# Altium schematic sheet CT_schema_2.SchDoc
size 384 x 228 mm
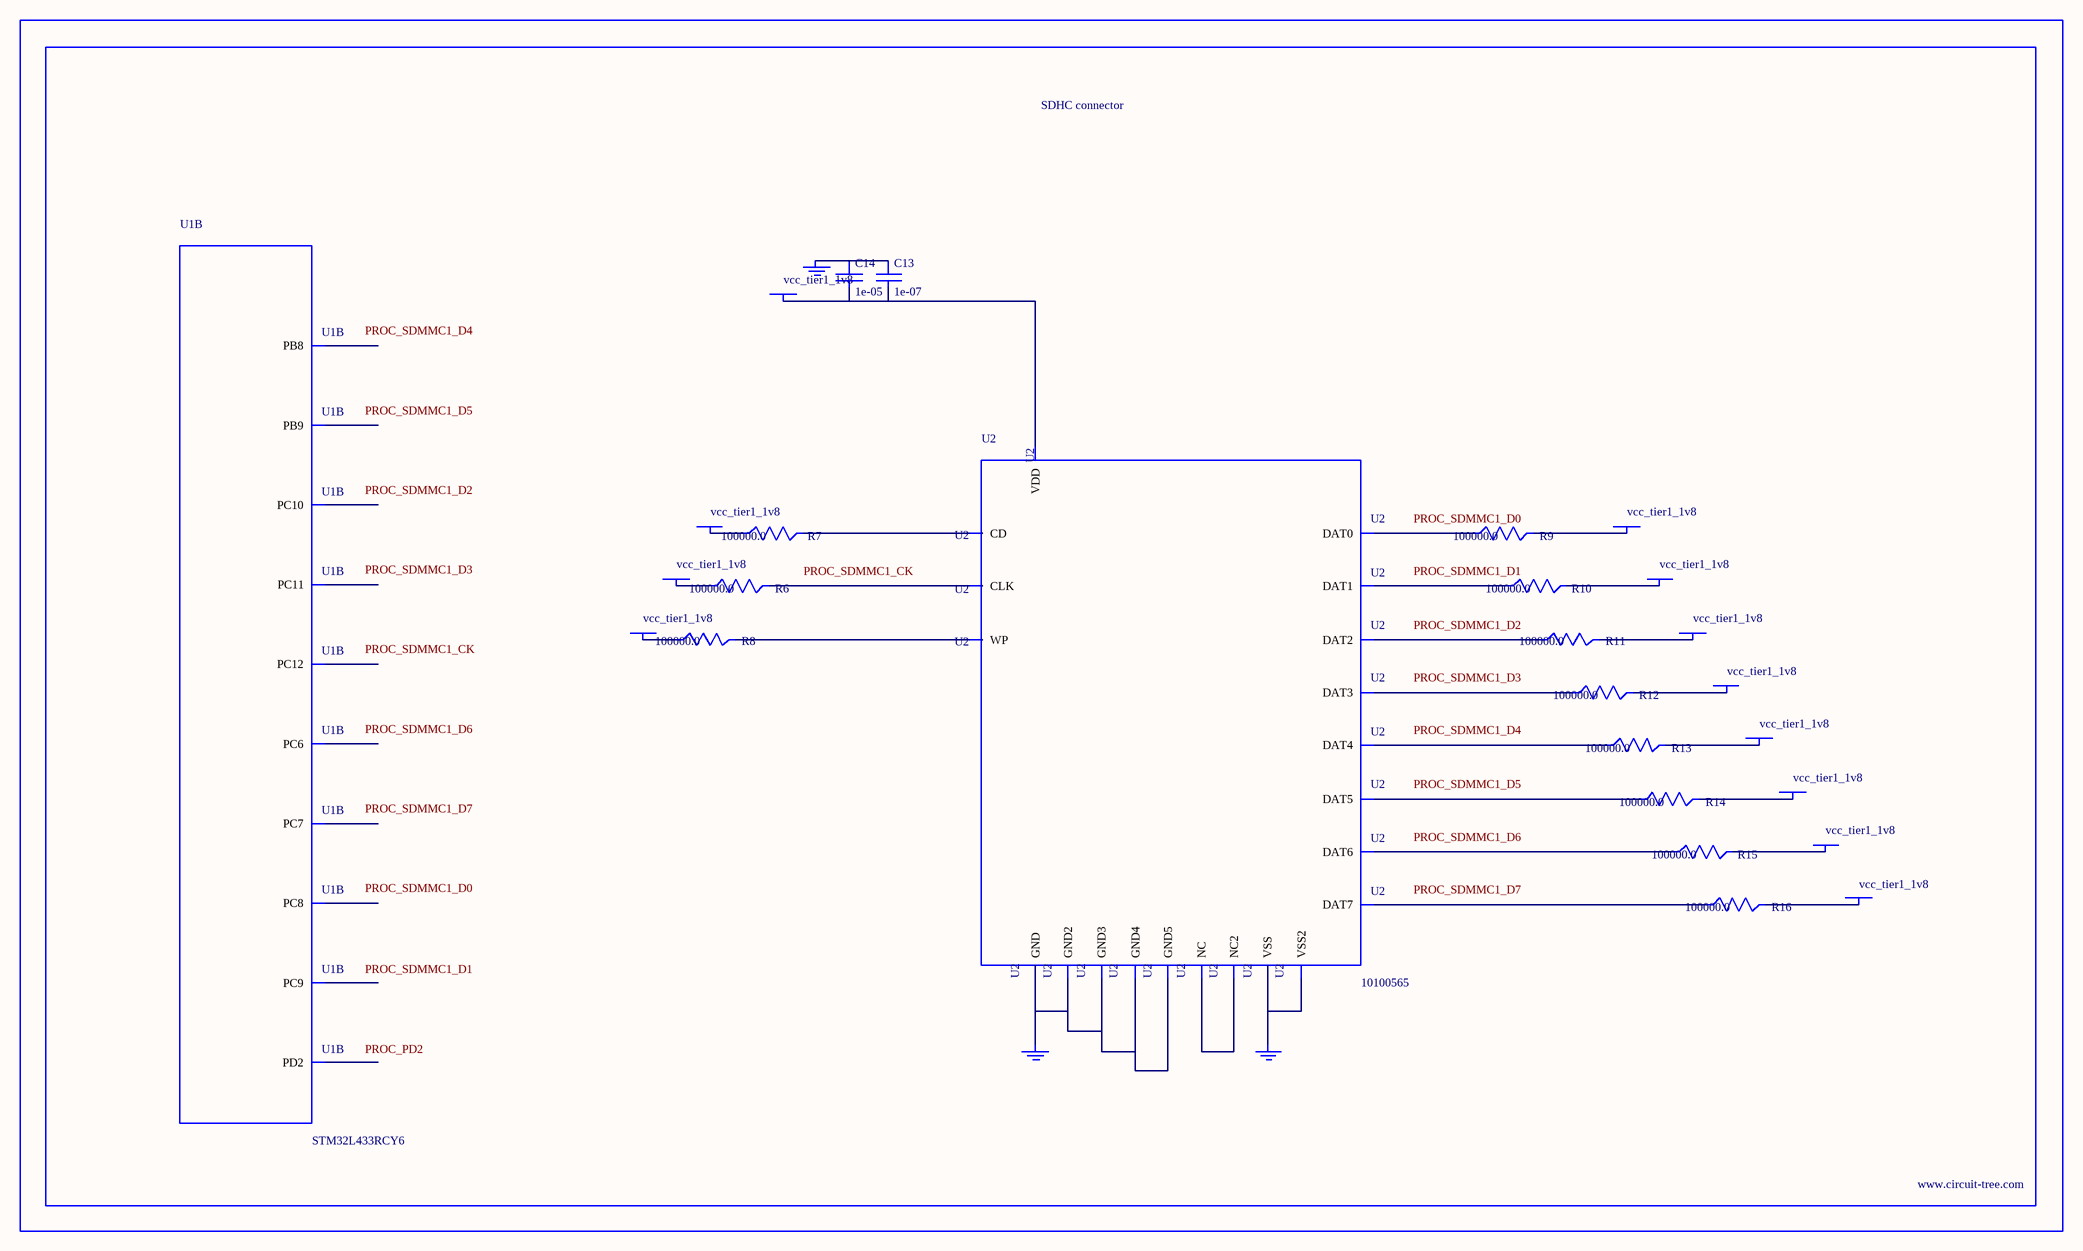
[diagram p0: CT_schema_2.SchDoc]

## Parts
BORDER1  (no value)
C13  1e-07  [C0402]
C14  1e-05  [C0805]
GND_INSTANCE_1_0  (no value)
GND_INSTANCE_1_1  (no value)
GND_INSTANCE_1_2  (no value)
POWER_INSTANCE_1_0  vcc_tier1_1v8
POWER_INSTANCE_1_1  vcc_tier1_1v8
POWER_INSTANCE_1_2  vcc_tier1_1v8
POWER_INSTANCE_1_3  vcc_tier1_1v8
POWER_INSTANCE_1_4  vcc_tier1_1v8
POWER_INSTANCE_1_5  vcc_tier1_1v8
POWER_INSTANCE_1_6  vcc_tier1_1v8
POWER_INSTANCE_1_7  vcc_tier1_1v8
POWER_INSTANCE_1_8  vcc_tier1_1v8
POWER_INSTANCE_1_9  vcc_tier1_1v8
POWER_INSTANCE_1_10  vcc_tier1_1v8
POWER_INSTANCE_1_11  vcc_tier1_1v8
R6  100000.0  [R0603]
R7  100000.0  [R0603]
R8  100000.0  [R0603]
R9  100000.0  [R0603]
R10  100000.0  [R0603]
R11  100000.0  [R0603]
R12  100000.0  [R0603]
R13  100000.0  [R0603]
R14  100000.0  [R0603]
R15  100000.0  [R0603]
R16  100000.0  [R0603]
U1  STM32L433RCY6  [WLCSP64]  (part B of 8)
U2  10100565  [10100565]

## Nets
NetC13_1: C13.1 C14.1 GND_INSTANCE_1_0.0(GND)
NetC13_2: C13.2 C14.2 POWER_INSTANCE_1_7.0(PWR) U2.9(VDD)
NetGND_INSTANCE_1_1_0: GND_INSTANCE_1_1.0(GND) U2.6(VSS) U2.10(VSS2)
NetGND_INSTANCE_1_2_0: GND_INSTANCE_1_2.0(GND) U2.12(GND) U2.16(GND2) U2.17(GND3) U2.20(GND4) U2.21(GND5)
NetPOWER_INSTANCE_1_0_0: POWER_INSTANCE_1_0.0(PWR) R8.1
NetPOWER_INSTANCE_1_1_0: POWER_INSTANCE_1_1.0(PWR) R7.1
NetPOWER_INSTANCE_1_2_0: POWER_INSTANCE_1_2.0(PWR) R10.2
NetPOWER_INSTANCE_1_3_0: POWER_INSTANCE_1_3.0(PWR) R9.2
NetPOWER_INSTANCE_1_4_0: POWER_INSTANCE_1_4.0(PWR) R16.2
NetPOWER_INSTANCE_1_5_0: POWER_INSTANCE_1_5.0(PWR) R15.2
NetPOWER_INSTANCE_1_6_0: POWER_INSTANCE_1_6.0(PWR) R6.1
NetPOWER_INSTANCE_1_8_0: POWER_INSTANCE_1_8.0(PWR) R14.2
NetPOWER_INSTANCE_1_9_0: POWER_INSTANCE_1_9.0(PWR) R13.2
NetPOWER_INSTANCE_1_10_0: POWER_INSTANCE_1_10.0(PWR) R12.2
NetPOWER_INSTANCE_1_11_0: POWER_INSTANCE_1_11.0(PWR) R11.2
NetR6_2: R6.2 U2.8(CLK)
NetR7_2: R7.2 U2.2(CD)
NetR8_2: R8.2 U2.1(WP)
NetR9_1: R9.1 U2.4(DAT0)
NetR10_1: R10.1 U2.3(DAT1)
NetR11_1: R11.1 U2.15(DAT2)
NetR12_1: R12.1 U2.14(DAT3)
NetR13_1: R13.1 U2.13(DAT4)
NetR14_1: R14.1 U2.11(DAT5)
NetR15_1: R15.1 U2.7(DAT6)
NetR16_1: R16.1 U2.5(DAT7)
NetU2_18: U2.18(NC) U2.19(NC2)

Not connected (* = marked no-connect by the designer): U1 A3(PC12) A4(PD2) B3(PC11) B6(PB9) C3(PC10) C6(PB8) E1(PC7) E2(PC9) F1(PC6) F3(PC8)

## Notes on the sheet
- Labels drawn without touching a wire or pin: PROC_PD2, PROC_SDMMC1_CK, PROC_SDMMC1_D0, PROC_SDMMC1_D1, PROC_SDMMC1_D2, PROC_SDMMC1_D3, PROC_SDMMC1_D4, PROC_SDMMC1_D5, PROC_SDMMC1_D6, PROC_SDMMC1_D7

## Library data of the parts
BORDER1 = BORDER_PAGE1
C13 = C0402C104K3RACTU
C14 = C0805C106K8RACTU
GND_INSTANCE_1_0-GND_INSTANCE_1_2 = GND
POWER_INSTANCE_1_0-POWER_INSTANCE_1_11 = PWR
R6-R16 = RC0603JR-07100KL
